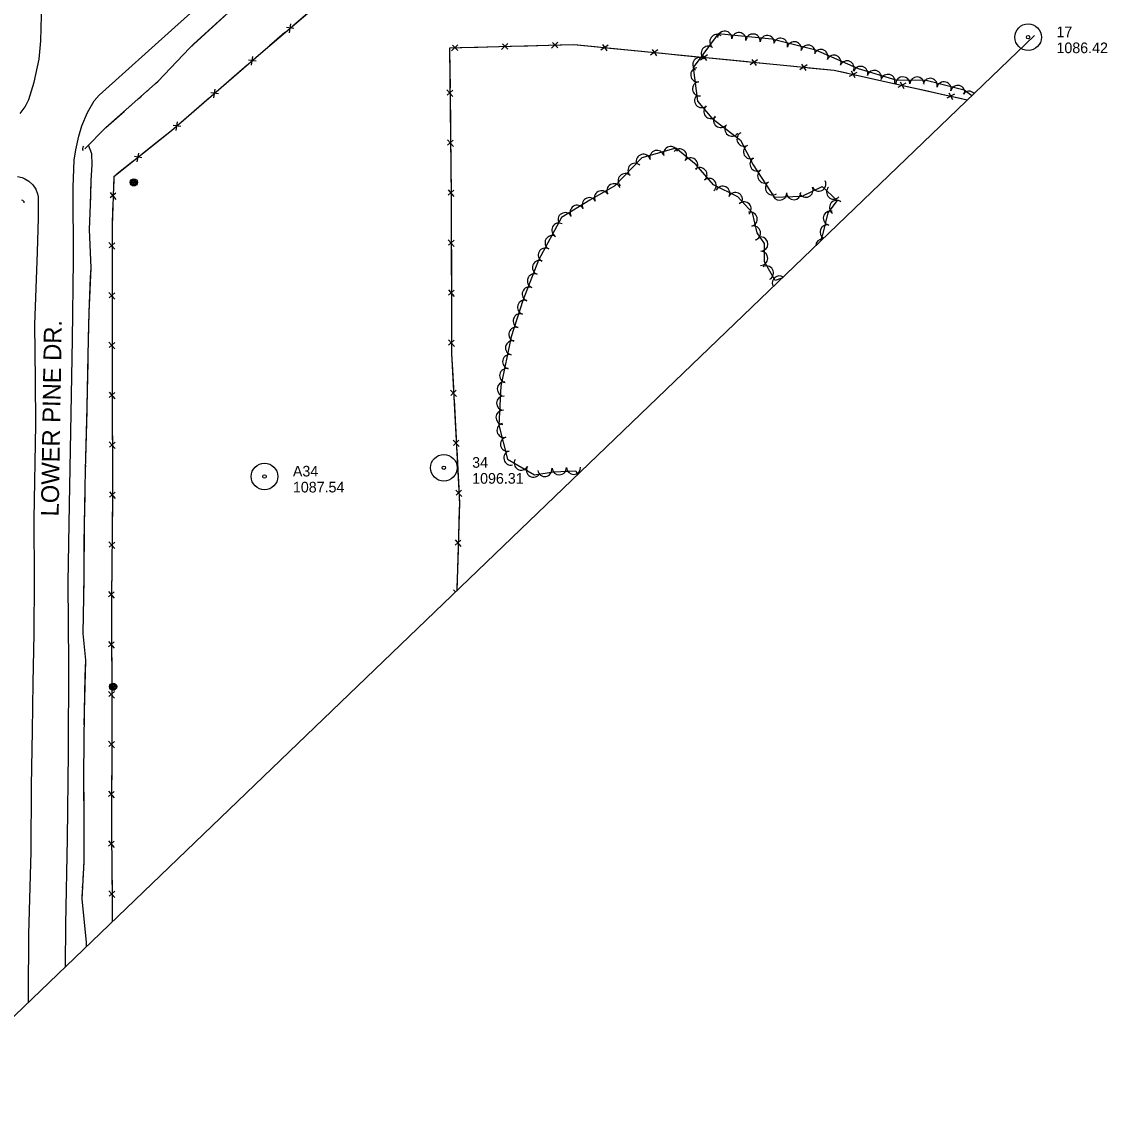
# Model space of a CAD drawing. Extents: x 295302 to 297577, y 27143 to 29590.
# Drawn here: x 296296 to 296908, y 27998 to 28612 of the extents above; entities that cross this region are included whole.
import ezdxf

# ---------------------------------------------------------------- set-up
doc = ezdxf.new("R2010")
doc.units = 0
for name, color, linetype in [('Level 11', 7, 'Continuous'), ('Level 14', 7, 'Continuous'), ('Level 15', 7, 'Continuous'), ('Level 18', 7, 'Continuous'), ('Level 19', 7, 'Continuous'), ('Level 4', 7, 'Continuous'), ('Level 6', 7, 'Continuous')]:
    doc.layers.add(name, color=color, linetype=linetype)

msp = doc.modelspace()

# ---------------------------------------------------------------- linework, layer by layer
at = {"layer": 'Level 11'}
for points in [[(296294.87, 28559.97), (296297.65, 28563.85), (296299.73, 28567.96), (296302.82, 28577.65), (296305.56, 28590.72), (296306.48, 28601.01), (296307.72, 28644.03), (296306.49, 28680.46), (296305.66, 28720), (296302.68, 28756.98), (296296.5, 28808.21), (296289.55, 28844.57)], [(296320.35, 28079.16), (296320.67, 28103.18), (296321.51, 28151.23), (296322.11, 28200.07), (296322.37, 28249.78), (296321.99, 28295.71), (296322.69, 28339.69), (296323.56, 28390.99), (296324.42, 28432.68), (296324.91, 28477.37), (296324.81, 28518.59), (296325.36, 28533.69), (296326.19, 28539.58), (296327.87, 28547.22), (296329.64, 28552.99), (296332.83, 28560.67), (296336.54, 28567.15), (296339.5, 28570.38), (296382.14, 28608.65), (296411.83, 28635.34)], [(296293.46, 28524.51), (296295.97, 28523.95), (296297.57, 28523.28), (296299.83, 28521.83), (296302.1, 28519.75), (296303.72, 28517.35), (296304.72, 28514.83), (296305.1, 28513.13), (296305.06, 28501.22), (296304.41, 28481.82), (296303.02, 28441.04), (296303.41, 28409.69), (296303.54, 28384.71), (296302.67, 28331.44), (296302.71, 28297.17), (296302.52, 28266.74), (296302.06, 28239.23), (296301.66, 28212.07), (296301.12, 28181.1), (296300.83, 28143.89), (296299.59, 28097.47), (296299.37, 28063.16), (296299.39, 28059.02)]]:
    msp.add_lwpolyline(points, dxfattribs=at)
at = {"layer": 'Level 14'}
for centre, radius in [((296358.95, 28521.2), 2.02), ((296358.93, 28521.21), 1.52), ((296358.97, 28521.18), 1.01), ((296358.96, 28521.19), 0.502), ((296347.27, 28236.99), 2.02), ((296347.26, 28237), 1.52), ((296347.29, 28236.98), 1.01), ((296347.29, 28236.99), 0.502)]:
    msp.add_circle(centre, radius, dxfattribs=at)
at = {"layer": 'Level 15'}
for p, q in [((296447.16, 28610.46), (296446.43, 28605.53)), ((296449.15, 28607.86), (296444.93, 28608.46)), ((296541.59, 28598.72), (296537.92, 28595.34)), ((296541.5, 28595.44), (296538.59, 28598.57)), ((296569.76, 28599.5), (296566.09, 28596.12)), ((296569.68, 28596.22), (296566.77, 28599.35)), ((296597.94, 28600.27), (296594.27, 28596.89)), ((296597.86, 28596.99), (296594.94, 28600.12)), ((296626.25, 28598.61), (296622.19, 28595.72)), ((296625.76, 28595.36), (296623.26, 28598.83)), ((296425.8, 28592.17), (296425.11, 28587.25)), ((296654.3, 28595.83), (296650.24, 28592.94)), ((296653.81, 28592.59), (296651.31, 28596.06)), ((296682.36, 28593.05), (296678.29, 28590.16)), ((296681.86, 28589.81), (296679.36, 28593.28)), ((296709.91, 28587.03), (296707.41, 28590.5)), ((296427.81, 28589.59), (296423.58, 28590.16)), ((296710.41, 28590.28), (296706.34, 28587.39)), ((296738.46, 28587.5), (296734.39, 28584.61)), ((296737.97, 28584.26), (296735.47, 28587.73)), ((296766.48, 28583.19), (296762.1, 28580.81)), ((296765.6, 28580.03), (296763.54, 28583.78)), ((296404.57, 28573.76), (296403.88, 28568.83)), ((296535.44, 28573.32), (296538.75, 28569.59)), ((296538.72, 28573.18), (296535.54, 28570.32)), ((296794, 28577.08), (296789.62, 28574.7)), ((296793.12, 28573.92), (296791.05, 28577.66)), ((296406.58, 28571.17), (296402.35, 28571.74)), ((296821.52, 28570.97), (296817.13, 28568.59)), ((296820.64, 28567.81), (296818.57, 28571.55)), ((296383.34, 28555.34), (296382.65, 28550.41)), ((296385.35, 28552.76), (296381.12, 28553.33)), ((296535.73, 28545.13), (296539.05, 28541.4)), ((296539.01, 28544.99), (296535.83, 28542.13)), ((296363.47, 28535.02), (296359.27, 28535.76)), ((296361.57, 28537.68), (296360.67, 28532.79)), ((296536.03, 28516.94), (296539.35, 28513.22)), ((296539.31, 28516.81), (296536.13, 28513.94)), ((296348.88, 28515.18), (296345.57, 28512.49)), ((296345.62, 28515.48), (296348.74, 28511.61)), ((296344.91, 28487.32), (296348.17, 28483.57)), ((296348.17, 28487.15), (296344.98, 28484.33)), ((296536.15, 28488.77), (296539.43, 28485.02)), ((296539.42, 28488.6), (296536.22, 28485.77)), ((296344.92, 28459.22), (296348.19, 28455.47)), ((296348.18, 28459.05), (296344.99, 28456.22)), ((296536.23, 28460.58), (296539.52, 28456.83)), ((296539.51, 28460.42), (296536.31, 28457.58)), ((296344.93, 28431.11), (296348.2, 28427.36)), ((296348.2, 28430.94), (296345, 28428.12)), ((296536.31, 28432.39), (296539.6, 28428.64)), ((296539.59, 28432.23), (296536.39, 28429.39)), ((296344.98, 28403), (296348.26, 28399.26)), ((296348.24, 28402.84), (296345.05, 28400.01)), ((296537.41, 28404.14), (296540.88, 28400.56)), ((296540.69, 28404.14), (296537.64, 28401.15)), ((296538.89, 28375.99), (296542.36, 28372.41)), ((296542.17, 28375.99), (296539.11, 28373)), ((296345.07, 28374.9), (296348.35, 28371.16)), ((296348.34, 28374.74), (296345.15, 28371.9)), ((296345.16, 28346.79), (296348.44, 28343.05)), ((296348.43, 28346.63), (296345.24, 28343.8)), ((296540.37, 28347.84), (296543.84, 28344.26)), ((296543.65, 28347.84), (296540.59, 28344.85)), ((296344.94, 28318.71), (296348.17, 28314.93)), ((296348.21, 28318.51), (296344.98, 28315.72)), ((296543.35, 28319.55), (296540.06, 28316.82)), ((296540.09, 28319.82), (296543.24, 28315.96)), ((296344.66, 28290.61), (296347.89, 28286.83)), ((296347.93, 28290.4), (296344.7, 28287.62)), ((296539.19, 28291.65), (296540.21, 28290.4)), ((296344.68, 28262.48), (296347.96, 28258.74)), ((296347.95, 28262.32), (296344.76, 28259.49)), ((296344.75, 28234.38), (296348.02, 28230.63)), ((296348.02, 28234.21), (296344.82, 28231.39)), ((296344.74, 28206.28), (296348, 28202.52)), ((296348.01, 28206.1), (296344.81, 28203.29)), ((296344.67, 28178.17), (296347.93, 28174.42)), ((296347.94, 28178), (296344.73, 28175.18)), ((296344.66, 28150.05), (296347.96, 28146.33)), ((296347.93, 28149.91), (296344.76, 28147.06)), ((296344.95, 28121.94), (296348.25, 28118.23)), ((296348.22, 28121.81), (296345.05, 28118.95))]:
    msp.add_line(p, q, dxfattribs=at)
for points in [[(296753.53, 28725.75), (296638.27, 28726.23), (296582.04, 28725.02), (296483.74, 28639.37), (296430.45, 28593.88), (296380.25, 28550.33), (296347.72, 28524.4), (296346.66, 28496.83), (296346.69, 28414.92), (296346.93, 28341.84), (296346.38, 28287.27), (296346.53, 28219.91), (296346.37, 28154.48), (296346.77, 28115.78), (296346.81, 28104.59)], [(296456.83, 28616.4), (296449.19, 28609.88)], [(296444.14, 28605.57), (296435.45, 28598.16)], [(296435.45, 28598.16), (296430.45, 28593.88), (296427.83, 28591.61)], [(296828.69, 28567.57), (296753.75, 28584.22), (296606.87, 28598.76), (296536.95, 28596.83), (296537.83, 28512.85), (296538.09, 28424.73), (296542.51, 28340.68), (296540.94, 28291.1)], [(296552.88, 28597.27), (296542.81, 28596.99)], [(296564.33, 28597.59), (296552.88, 28597.27)], [(296581.05, 28598.05), (296570.98, 28597.77)], [(296592.51, 28598.36), (296581.05, 28598.05)], [(296609.22, 28598.53), (296606.87, 28598.76), (296599.16, 28598.55)], [(296620.62, 28597.4), (296609.22, 28598.53)], [(296637.27, 28595.75), (296627.25, 28596.74)], [(296536.96, 28596.04), (296537.08, 28584.58)], [(296648.67, 28594.62), (296637.27, 28595.75)], [(296665.33, 28592.97), (296655.3, 28593.96)], [(296676.72, 28591.84), (296665.33, 28592.97)], [(296693.38, 28590.19), (296683.35, 28591.19)], [(296422.82, 28587.26), (296414.19, 28579.78)], [(296537.08, 28584.58), (296537.18, 28574.51)], [(296704.78, 28589.07), (296693.38, 28590.19)], [(296721.43, 28587.42), (296711.4, 28588.41)], [(296732.83, 28586.29), (296721.43, 28587.42)], [(296749.48, 28584.64), (296739.45, 28585.63)], [(296760.74, 28582.66), (296753.75, 28584.22), (296749.48, 28584.64)], [(296414.19, 28579.78), (296406.6, 28573.2)], [(296777.08, 28579.04), (296767.24, 28581.22)], [(296788.26, 28576.55), (296777.08, 28579.04)], [(296804.6, 28572.92), (296794.76, 28575.11)], [(296815.78, 28570.44), (296804.6, 28572.92)], [(296401.59, 28568.85), (296392.96, 28561.36)], [(296537.25, 28567.85), (296537.37, 28556.4)], [(296828.69, 28567.57), (296822.28, 28569)], [(296392.96, 28561.36), (296385.37, 28554.78)], [(296537.37, 28556.4), (296537.48, 28546.32)], [(296380.36, 28550.43), (296380.25, 28550.33), (296371.43, 28543.3)], [(296371.43, 28543.3), (296363.58, 28537.04)], [(296537.55, 28539.66), (296537.67, 28528.21)], [(296358.39, 28532.9), (296349.46, 28525.78)], [(296349.46, 28525.78), (296347.72, 28524.4), (296347.42, 28516.58)], [(296537.67, 28528.21), (296537.78, 28518.14)], [(296537.84, 28511.48), (296537.87, 28500.02)], [(296347.16, 28509.95), (296346.72, 28498.53)], [(296346.72, 28498.53), (296346.66, 28496.83), (296346.66, 28488.49)], [(296537.87, 28500.02), (296537.9, 28489.95)], [(296346.66, 28481.85), (296346.67, 28470.43)], [(296537.92, 28483.29), (296537.96, 28471.83)], [(296346.67, 28470.43), (296346.67, 28460.39)], [(296537.96, 28471.83), (296537.98, 28461.76)], [(296346.67, 28453.75), (296346.68, 28442.33)], [(296538, 28455.1), (296538.04, 28443.64)], [(296538.04, 28443.64), (296538.07, 28433.57)], [(296346.68, 28442.33), (296346.68, 28432.28)], [(296346.69, 28425.64), (296346.69, 28414.92), (296346.69, 28414.22)], [(296538.09, 28426.91), (296538.09, 28424.73), (296538.58, 28415.47)], [(296346.69, 28414.22), (296346.73, 28404.18)], [(296538.58, 28415.47), (296539.11, 28405.41)], [(296346.75, 28397.54), (296346.79, 28386.12)], [(296539.46, 28398.76), (296540.06, 28387.32)], [(296346.79, 28386.12), (296346.82, 28376.07)], [(296540.06, 28387.32), (296540.59, 28377.26)], [(296346.84, 28369.43), (296346.88, 28358.01)], [(296540.93, 28370.61), (296541.53, 28359.17)], [(296346.88, 28358.01), (296346.91, 28347.97)], [(296541.53, 28359.17), (296542.06, 28349.11)], [(296346.92, 28341.33), (296346.81, 28329.91)], [(296542.41, 28342.46), (296542.51, 28340.68), (296542.2, 28331.01)], [(296346.81, 28329.91), (296346.71, 28319.86)], [(296542.2, 28331.01), (296541.88, 28320.94)], [(296541.67, 28314.28), (296541.31, 28302.84)], [(296346.64, 28313.22), (296346.53, 28301.8)], [(296541.31, 28302.84), (296540.99, 28292.77)], [(296346.53, 28301.8), (296346.43, 28291.76)], [(296346.39, 28285.12), (296346.41, 28273.7)], [(296346.41, 28273.7), (296346.43, 28263.65)], [(296346.45, 28257.01), (296346.48, 28245.6)], [(296346.48, 28245.6), (296346.5, 28235.55)], [(296346.51, 28228.91), (296346.53, 28219.91), (296346.53, 28217.49)], [(296346.53, 28217.49), (296346.5, 28207.45)], [(296346.48, 28200.81), (296346.46, 28189.39)], [(296346.46, 28189.39), (296346.43, 28179.34)], [(296346.41, 28172.7), (296346.38, 28161.28)], [(296346.38, 28161.28), (296346.37, 28154.48), (296346.4, 28151.24)], [(296346.47, 28144.6), (296346.59, 28133.18)], [(296346.59, 28133.18), (296346.69, 28123.13)], [(296346.76, 28116.49), (296346.77, 28115.78), (296346.81, 28105.07)], [(296346.81, 28105.07), (296346.81, 28104.59)]]:
    msp.add_lwpolyline(points, dxfattribs=at)
for centre, radius, start, end in [((296331.46, 28540.26), 1.5, 122.78358, 229.02314), ((296295.91, 28509.93), 1.2, 345.86156, 92.10113)]:
    msp.add_arc(centre, radius, start, end, dxfattribs=at)
at = {"layer": 'Level 18'}
for points in [[(296831.24, 28570.02), (296827.01, 28573.08), (296805.45, 28578.62), (296788.57, 28578.89), (296767.42, 28585.13), (296743.33, 28595.64), (296718.52, 28601.83), (296688.22, 28604.95), (296674.17, 28585.95), (296676.59, 28566.98), (296684.68, 28557.31), (296700.8, 28545.07), (296708.05, 28531.03), (296719.8, 28512.91), (296735.59, 28513.51), (296747.01, 28518.9), (296755.39, 28510.94), (296750.12, 28504), (296747.19, 28491.66), (296745.98, 28488.11)], [(296724.19, 28467.17), (296720.37, 28465.82), (296714.33, 28476.47), (296714.47, 28486.67), (296710.31, 28492.8), (296707.66, 28504.11), (296699.46, 28513.15), (296685.63, 28519.91), (296675.94, 28531.14), (296664.47, 28540.45), (296645.22, 28534.95), (296630.15, 28519.18), (296615.93, 28511.21), (296599.96, 28501.32), (296586.98, 28477.36), (296578.27, 28454.7), (296571.6, 28434.07), (296565.77, 28406.44), (296564.74, 28384.37), (296569.51, 28365.15), (296584.69, 28356.38), (296595.54, 28358.07), (296608.05, 28358.59), (296609.11, 28356.6)]]:
    msp.add_lwpolyline(points, dxfattribs=at)
for centre, start, end in [((296687.53, 28600.48), 53.51012, 233.49479), ((296692, 28602.45), 354.12895, 174.11362), ((296699.97, 28601.63), 354.12895, 174.11362), ((296707.94, 28600.81), 354.12895, 174.11362), ((296715.92, 28599.99), 354.12895, 174.11362), ((296682.76, 28594.04), 53.51012, 233.49479), ((296723.46, 28598.43), 346.00837, 165.99305), ((296731.23, 28596.49), 346.00837, 165.99305), ((296739.01, 28594.56), 346.00837, 165.99305), ((296678, 28587.6), 53.51012, 233.49479), ((296746.24, 28592.08), 336.44443, 156.42911), ((296753.58, 28588.88), 336.44443, 156.42911), ((296676.8, 28581.84), 97.28614, 277.27082), ((296760.93, 28585.68), 336.44443, 156.42911), ((296768.6, 28582.6), 343.57296, 163.55764), ((296776.28, 28580.33), 343.57296, 163.55764), ((296783.97, 28578.07), 343.57296, 163.55764), ((296792.37, 28576.73), 359.06391, 179.04859), ((296800.38, 28576.6), 359.06391, 179.04859), ((296807.82, 28575.84), 345.61623, 165.60091), ((296677.82, 28573.89), 97.28614, 277.27082), ((296815.58, 28573.85), 345.61623, 165.60091), ((296823.34, 28571.86), 345.61623, 165.60091), ((296829.64, 28568.59), 42.76635, 144.09179), ((296679.04, 28567.32), 129.92499, 309.90967), ((296684.18, 28561.17), 129.92499, 309.90967), ((296689.72, 28556.12), 142.81961, 322.80429), ((296696.1, 28551.27), 142.81961, 322.80429), ((296702.9, 28545.57), 117.31046, 297.29513), ((296661.54, 28537.43), 15.94638, 195.93105), ((296706.58, 28538.45), 117.31046, 297.29513), ((296646.12, 28533.03), 15.94638, 195.93105), ((296653.83, 28535.23), 15.94638, 195.93105), ((296666.53, 28536.07), 320.92867, 140.91334), ((296641.44, 28527.96), 46.33194, 226.31661), ((296672.76, 28531.02), 320.92867, 140.91334), ((296678.02, 28525.52), 310.80294, 130.78762), ((296710.22, 28531.55), 122.96269, 302.94737), ((296635.9, 28522.16), 46.33194, 226.31661), ((296683.26, 28519.45), 310.80294, 130.78762), ((296714.57, 28524.82), 122.96269, 302.94737), ((296629.53, 28516.43), 29.24766, 209.23233), ((296690.83, 28515.04), 333.96011, 153.94479), ((296718.93, 28518.1), 122.96269, 302.94737), ((296737.78, 28516.86), 205.28368, 25.26835), ((296745.03, 28520.28), 205.28368, 25.26835), ((296753.4, 28515.73), 136.51242, 316.4971), ((296615.67, 28508.58), 31.8016, 211.78628), ((296622.54, 28512.51), 29.24766, 209.23233), ((296698.03, 28511.52), 333.96011, 153.94479), ((296722.91, 28515.12), 182.17236, 2.15704), ((296730.91, 28515.43), 182.17236, 2.15704), ((296755.08, 28507.07), 52.8235, 232.80818), ((296608.85, 28504.36), 31.8016, 211.78628), ((296702.91, 28506.23), 312.2021, 132.18678), ((296751.57, 28501.01), 76.6296, 256.61428), ((296602.04, 28500.14), 31.8016, 211.78628), ((296706.36, 28500.46), 283.21314, 103.19782), ((296598.54, 28494.28), 61.56019, 241.54486), ((296708.19, 28492.66), 283.21314, 103.19782), ((296749.71, 28493.21), 76.6296, 239.7404), ((296594.72, 28487.24), 61.56019, 241.54486), ((296712.37, 28486.44), 269.20445, 89.18913), ((296747.27, 28485.38), 89.38617, 178.32344), ((296590.9, 28480.19), 61.56019, 241.54486), ((296712.26, 28478.43), 269.20445, 89.18913), ((296587.63, 28473.19), 68.97608, 248.96076), ((296715.5, 28470.14), 299.57154, 119.55622), ((296584.75, 28465.71), 68.97608, 248.96076), ((296722.82, 28464.46), 58.37339, 199.54097), ((296581.87, 28458.23), 68.97608, 248.96076), ((296579.21, 28450.8), 72.07752, 252.0622), ((296576.74, 28443.17), 72.07752, 252.0622), ((296574.28, 28435.55), 72.07752, 252.0622), ((296572.45, 28427.98), 78.09654, 258.08122), ((296570.8, 28420.14), 78.09654, 258.08122), ((296569.15, 28412.3), 78.09654, 258.08122), ((296567.79, 28404.76), 87.34574, 267.33042), ((296567.42, 28396.75), 87.34574, 267.33042), ((296567.04, 28388.75), 87.34574, 267.33042), ((296567.63, 28381.45), 103.95548, 283.94016), ((296569.56, 28373.67), 103.95548, 283.94016), ((296571.49, 28365.89), 103.95548, 283.94016), ((296577.29, 28363.08), 149.9769, 329.96158), ((296584.23, 28359.07), 149.9769, 329.96158), ((296590.56, 28359.42), 188.87559, 8.86027), ((296598.75, 28360.31), 182.38713, 2.37181), ((296606.76, 28360.64), 182.38713, 2.37181)]:
    msp.add_arc(centre, 4.01, start, end, dxfattribs=at)
at = {"layer": 'Level 19'}
for points in [[(296331.27, 28540.05), (296343.21, 28552.17), (296372.71, 28578.2), (296390.25, 28596.86), (296425.43, 28629.21), (296453.85, 28655.82), (296482.43, 28683.39), (296505.41, 28703.49), (296518.38, 28714.25)], [(296392.67, 28599.09), (296415.42, 28620.01)], [(296371.2, 28576.88), (296372.71, 28578.2), (296390.25, 28596.86), (296392.67, 28599.09)], [(296366.41, 28572.65), (296368.01, 28574.06)], [(296361.61, 28568.41), (296363.21, 28569.83)], [(296331.27, 28540.05), (296343.21, 28552.17), (296353.62, 28561.36)], [(296356.82, 28564.18), (296358.42, 28565.59)], [(296332.29, 28090.64), (296332.36, 28092.77), (296329.78, 28117.52), (296330.89, 28138.31), (296331.03, 28157.18), (296330.77, 28187.87), (296331.1, 28223.09), (296331.84, 28251.91), (296330.41, 28267.03), (296330.89, 28297.67), (296331.13, 28328.57), (296331.78, 28359.05), (296332.69, 28394.7), (296333.2, 28424.06), (296333.7, 28447.93), (296334.81, 28473.07), (296333.91, 28494.63), (296334.7, 28513.48), (296334.91, 28522), (296335.38, 28531.2), (296335.29, 28537.38), (296333.36, 28542.18)], [(296334.75, 28515.43), (296334.91, 28522), (296335.38, 28531.2), (296335.29, 28537.38), (296333.36, 28542.18)], [(296334.54, 28509.81), (296334.62, 28511.69)], [(296334.31, 28504.19), (296334.39, 28506.07)], [(296334.08, 28498.57), (296334.15, 28500.45)], [(296334.57, 28467.66), (296334.81, 28473.07), (296333.91, 28494.63), (296333.92, 28494.83)], [(296333.54, 28440.48), (296333.7, 28447.93), (296334.57, 28467.66)], [(296333.31, 28429.23), (296333.35, 28431.11)], [(296333.43, 28434.86), (296333.47, 28436.73)], [(296333.19, 28423.61), (296333.2, 28424.06), (296333.23, 28425.48)], [(296332.64, 28392.67), (296332.69, 28394.7), (296333.13, 28419.86)], [(296331.94, 28365.48), (296332.64, 28392.67)], [(296331.8, 28359.85), (296331.85, 28361.73)], [(296331.68, 28354.23), (296331.72, 28356.1)], [(296331.56, 28348.6), (296331.6, 28350.48)], [(296331.05, 28317.66), (296331.13, 28328.57), (296331.48, 28344.85)], [(296330.78, 28290.47), (296330.89, 28297.67), (296331.05, 28317.66)], [(296330.69, 28284.84), (296330.72, 28286.71)], [(296330.6, 28279.21), (296330.63, 28281.09)], [(296330.51, 28273.59), (296330.54, 28275.46)], [(296331.6, 28242.71), (296331.84, 28251.91), (296330.41, 28267.03), (296330.45, 28269.83)], [(296331.03, 28215.52), (296331.1, 28223.09), (296331.6, 28242.71)], [(296330.98, 28209.89), (296330.99, 28211.77)], [(296330.92, 28204.26), (296330.94, 28206.14)], [(296330.87, 28198.64), (296330.89, 28200.51)], [(296330.94, 28167.69), (296330.77, 28187.87), (296330.84, 28194.89)], [(296330.9, 28140.5), (296331.03, 28157.18), (296330.94, 28167.69)], [(296330.7, 28134.88), (296330.8, 28136.75)], [(296330.4, 28129.26), (296330.5, 28131.13)], [(296330.1, 28123.64), (296330.2, 28125.52)], [(296332.36, 28092.84), (296329.78, 28117.52), (296329.9, 28119.9)], [(296332.29, 28090.64), (296332.36, 28092.77), (296332.36, 28092.84)]]:
    msp.add_lwpolyline(points, dxfattribs=at)
at = {"layer": 'Level 4'}
msp.add_lwpolyline([(296117.92, 27884.67), (296866.66, 28604.06)], dxfattribs=at)
at = {"layer": 'Level 6'}
for centre, radius in [((296862.98, 28603.02), 7.5), ((296862.98, 28603.02), 0.96), ((296533.66, 28360.39), 7.5), ((296432.62, 28355.46), 7.5), ((296533.66, 28360.39), 0.96), ((296432.62, 28355.46), 0.96)]:
    msp.add_circle(centre, radius, dxfattribs=at)

# ---------------------------------------------------------------- texts
at = {"layer": 'Level 11'}
msp.add_text('LOWER PINE DR.', height=10, rotation=89.0802, dxfattribs=at).set_placement((296316.58, 28332.9))
at = {"layer": 'Level 6'}
for s, p in [('17', (296878.98, 28603.02)), ('1086.42', (296878.98, 28594.02)), ('34', (296549.66, 28360.39)), ('A34', (296448.62, 28355.46)), ('1096.31', (296549.66, 28351.39)), ('1087.54', (296448.62, 28346.46))]:
    msp.add_text(s, height=6, dxfattribs=at).set_placement(p)

doc.saveas('drawing.dxf')
